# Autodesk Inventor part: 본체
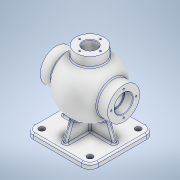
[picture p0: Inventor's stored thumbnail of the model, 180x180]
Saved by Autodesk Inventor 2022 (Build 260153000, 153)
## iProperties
Created: 2024-04
Part Number: 본체
Material: 알루미늄 6061
Document SubType Name: Modeling
Designer: Admin
Mass: 1526.73 g
Surface Area: 1173.98 cm^2
Volume: 565.456 cm^3
Density: 2.7 g/cm^3
Appearance: 알루미늄 - 평지
Author: Admin
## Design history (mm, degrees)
sketch "스케치2"
  geometry: L1 (-149.25, 0)-(163.578, 0); A1 r 54 centre (0, 0) between (54, 0) and (-54, 0); 1 further point
  constraints: 3 point on line, 2 end point, 2 point on circle, 1 centre point, 1 coincident, 1 horizontal
  dimensions: "d6" = 108 diameter of A1
revolve "회전1" sketch "스케치2" stored, may be unused: angle "d7" = 90 deg
node "작업 평면1"
sketch "스케치3"
  geometry: L1 (62.5, 62.5)-(-62.5, 62.5); L2 (-62.5, 62.5)-(-62.5, -62.5); L3 (-62.5, -62.5)-(62.5, -62.5); L4 (62.5, -62.5)-(62.5, 62.5); L5 (62.5, 62.5)-(-62.5, -62.5); L6 (-62.5, 62.5)-(62.5, -62.5); 1 further point
  constraints: 12 end point, 2 midpoint, 2 parallel, 1 horizontal, 1 perpendicular
  dimensions: "d9" = 125 distance of L2.end L3.end; "d10" = 125 distance of L1.end L2.end
extrude "돌출2" join sketch "스케치3" distance "d11" = 10; taper "d12" = 0 deg
sketch "스케치4"
  geometry: L1 (-75, 62.5)-(-75, -62.5) reference; L2 (-75, 50.5)-(0, 23.202); L3 (0, 23.202)-(0, -23.202); L4 (0, -23.202)-(-75, -50.5); L5 (-75, 50.5)-(-75, -50.5); L6 (-85, -62.5)-(-75, -62.5) reference; L7 (-85, 62.5)-(-75, 62.5) reference; 1 further point
  constraints: 8 end point, 2 parallel, 2 point on line, 1 midpoint
  dimensions: "d13" = 20 deg angle of L6 L4; "d14" = 12 distance from line of L6 L4.end; "d15" = 12 distance from line of L2.start L7; "d16" = 20 deg angle of L7 L2
extrude "돌출3" join sketch "스케치4" stored distance "d17" = 8; taper "d18" = 0 deg
sketch "스케치5"
  geometry: L1 (-62.5, -75)-(62.5, -75) reference; L2 (50.5, -75)-(23.202, 0); L3 (23.202, 0)-(-23.202, 0); L4 (-23.202, 0)-(-50.5, -75); L5 (50.5, -75)-(-50.5, -75); L6 (62.5, -85)-(62.5, -75) reference; L7 (-62.5, -85)-(-62.5, -75) reference; 1 further point
  constraints: 8 end point, 2 parallel, 2 point on line, 1 midpoint
  dimensions: "d19" = 20 deg angle of L6 L2; "d20" = 12 distance from line of L6 L2.start; "d21" = 12 distance from line of L7 L4.end; "d22" = 20 deg angle of L7 L4
extrude "돌출4" join sketch "스케치5" stored distance "d23" = 8; taper "d24" = 0 deg
sketch "스케치6"
  geometry: C1 r 31 at (0, 0); 1 further point
  constraints: 1 centre point, 1 coincident
  dimensions: "d25" = 62 diameter of C1
extrude "돌출5" join sketch "스케치6" stored distance "d26" = 130; taper "d27" = 0 deg
node "작업 평면2"
sketch "스케치7"
  geometry: C1 r 27 at (0, 0); 1 further point
  constraints: 1 centre point, 1 coincident
  dimensions: "d29" = 54 diameter of C1
extrude "돌출6" join sketch "스케치7" distance "d30" = 40; taper "d31" = 0 deg
sketch "스케치8"
  geometry: L1 (87.11, 0)-(-91.059, 0); L2 (65, 0)-(49, 0); L3 (49, 0)-(49, 17.5); L4 (49, 17.5)-(65, 17.5); L5 (65, 17.5)-(65, 0); L6 (49, 0)-(44, 0); L7 (41.364, 15)-(49, 15); L8 (49, 15)-(49, 0); L9 (-65, 0)-(-49, 0); L10 (-49, 0)-(-49, 17.5); L11 (-49, 17.5)-(-65, 17.5); L12 (-65, 17.5)-(-65, 0); L13 (-49, 0)-(-44, 0); L14 (-41.364, 15)-(-49, 15); L15 (-49, 15)-(-49, 0); L16 (65, -31)-(65, 31) reference; L17 (-65, 31)-(-65, -31) reference; L18 (44, 0)-(-44, 0); L19 (-44.215, -31)-(-44.215, 31) reference; A1 r 44 centre (0, 0) between (44, 0) and (-44, 0); 3 further points
  constraints: 32 end point, 6 parallel, 5 horizontal, 4 point on circle, 3 perpendicular, 3 point on line, 2 midpoint, 1 centre point, 1 coincident
  dimensions: "d32" = 88 diameter of A1; "d33" = 35 diameter of L4 L1; "d34" = 30 diameter of L7 L1; "d35" = 16 distance of L3.end L4.end; "d36" = 35 diameter of L11 L1; "d37" = 16 distance of L10.end L11.end; "d38" = 30 diameter of L14 L1
revolve "회전2" sketch "스케치8" stored, may be unused: angle "d39" = 90 deg
sketch "스케치9"
  geometry: C1 r 13 at (0, 0); 1 further point
  constraints: 1 centre point, 1 coincident
  dimensions: "d40" = 26 diameter of C1
extrude "돌출7" cut sketch "스케치9" distance "d41" = 40; taper "d42" = 0 deg
chamfer "모따기1" distance "d43" = 1; stored, may be unused: second distance "d44" = 2, angle "d45" = 45 deg
fillet "모깎기1" dims "d46" = 0.6
sketch "스케치10" dims "d47" = 48
  geometry: L1 (0, -115)-(0, 95) reference; 3 further points
  constraints: 1 coincident, 1 point on line, 1 vertical alignment, 2 other
hole "구멍1" sketch "스케치10" at (0, 24) diameter "d48" = 3.242; stored, may be unused: countersink angle "d52" = 90 deg, drill point angle "d54" = 118 deg; dims "d49" = 12, "d50" = 4, "d51" = 2, "d53" = 15
sketch "스케치11" dims "d58" = 40
  geometry: L1 (0, 87.5)-(0, -87.5) reference; 3 further points
  constraints: 1 coincident, 1 point on line, 1 vertical alignment, 2 other
hole "구멍2" sketch "스케치11" at (0, -20) diameter "d59" = 3.242; stored, may be unused: countersink angle "d63" = 90 deg, drill point angle "d65" = 118 deg; dims "d60" = 9, "d61" = 4, "d62" = 2, "d64" = 11
fillet "모깎기2" dims "d69" = 16
sketch "스케치12"
  geometry: C1 r 5.5 at (-46.5, -46.5); C2 r 5.5 at (-46.5, 46.5); C3 r 5.5 at (46.5, 46.5); C4 r 5.5 at (46.5, -46.5); A1 r 16 centre (-46.5, -46.5) between (-62.5, -46.5) and (-46.5, -62.5) reference; A2 r 16 centre (-46.5, 46.5) between (-46.5, 62.5) and (-62.5, 46.5) reference; A3 r 16 centre (46.5, 46.5) between (62.5, 46.5) and (46.5, 62.5) reference; A4 r 16 centre (46.5, -46.5) between (46.5, -62.5) and (62.5, -46.5) reference; 1 further point
  constraints: 4 centre point, 4 coincident
  dimensions: "d70" = 11 diameter of C1; "d71" = 11 diameter of C2; "d72" = 11 diameter of C3; "d73" = 11 diameter of C4
extrude "돌출8" cut sketch "스케치12" extent not by distance; stored distance "d74" = 0; taper "d75" = 0 deg
fillet "모깎기3" dims "d76" = 3
fillet "모깎기4" dims "d77" = 3
fillet "모깎기5" dims "d78" = 3
fillet "모깎기6" dims "d79" = 3
node "작업 평면3"
sketch "스케치13"
  geometry: L1 (27, 65)-(-27, 65) reference; L2 (0, -115)-(0, 95) reference; 2 further points
  constraints: 1 point on line, 1 other
  dimensions: "d81" = 9 distance from line of L1 point (0, 56)
feature "엠보싱1" sketch "스케치13" dims "d6" = 108, "d82" = 0.5, "d83" = 0
node "솔리드2"
pattern_circular "원형 패턴1" dims angle "d56" = 360 deg
mirror "미러1"
pattern_circular "원형 패턴2" dims angle "d67" = 360 deg
feature "A9D066F2-1C7D-4E18-AEED-F7BC21143FA4" dims "d48" = 3.242, "d49" = 12, "d50" = 4, "d51" = 2, "d52" = 90 deg, "d53" = 15, "d54" = 118 deg
other parameters: "d8" = -85, "d28" = 65, "d80" = -85.75
